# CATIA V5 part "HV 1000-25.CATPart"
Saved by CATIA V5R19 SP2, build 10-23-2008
Part number: HV 1000-25
Bounding box of the stored display mesh (mm): x -24.865 to 24.865, y -24.997 to 24.997, z 0 to 107
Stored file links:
  C:\Users\Bora\Desktop\3D KATI MODEL- CATIA PART\HV serisi\HV 1000\HV 1000-25.CATPart
  C:\Program Files\Dassault Systemes\B19\intel_a\reffiles\standard\MetricThickPitch.txt
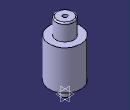
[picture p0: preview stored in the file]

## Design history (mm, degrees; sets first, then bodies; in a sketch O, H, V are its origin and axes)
Body1 (main body)
  Sketch1 on yz-plane, origin (0, 0, 0), H (0, 1, 0), V (0, 0, 1)
    point P1 (14, 105)
    point P3 (14, 105)
    point P8 (8, 17)
    point P10 (8, 1)
    point P11 (8, 17)
    point P12 (8, 1)
    arc A1 centre (12, 105) radius 2 from (14, 105) to (12, 107) ccw
    line L1 (14, 105) -> (14, 81)
    arc A2 centre (8, 18) radius 1 from (8, 19) to (8, 17) ccw
    line L2 (7, 0) -> (8, 1)
    line L3 (8, 17) -> (8, 1)
    line L4 (0, 0) -> (7, 0)
    line L5 (8, 19) -> (25, 19)
    line L6 (14, 81) -> (25, 81)
    line L7 (12, 107) -> (0, 107)
    point P13 (0, 107)
    line L8 (25, 81) -> (25, 19)
    horizontal: L4 H, L5 H, L6 H
    coincidence: P13 V, P1 P3, P8 P11, P10 P12
    tangency: L7 A1
    vertical: L8 V
  Shaft1: profile Sketch1, axis Sketch1.V, angle 360
  Sketch2 on face of Shaft1 from Sketch1.L4, origin (0, 0, 0), H (1, 0, 0), V (0, -1, 0)
    point P1 (0, 0)
  Hole1: placed by Sketch2, at (0, 0, 0) direction (0, 0, 1), diameter 13.835, depth 19, threaded "M16", thread diameter 16, thread depth 19, pitch 2
  Sketch3 on face of Shaft1 from Sketch1.L7, origin (0, 0, 107), H (1, 0, 0), V (0, 1, 0)
    point P1 (0, 0)
  Hole2: placed by Sketch3, at (0, 0, 107) direction (0, 0, -1), diameter 6.647, depth 15, threaded "M8", thread diameter 8, thread depth 15, pitch 1.25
